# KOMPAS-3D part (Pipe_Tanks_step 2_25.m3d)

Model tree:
1. X Axis
2. Y Axis
3. Z Axis  (labels: Pipe Dn 50; T-Bend Dn 50)
     Òîëùèíà ñòåíêè 1 = 1

Referenced files in C:\Documents and Settings\kashirsky\Мои документы\Camtasia Studio\Pipelines3D\Tanks\: Tanks_step 2.a3d
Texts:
  Pipe Dn 50
  Steel ASTM A295
  Three Point Plane
  Plane at Angle
  Line and Point Plane
  Axis through Two Vertices
  Axis of Feature
  Axis of Conical Surface
  Axis through Edge
  Trim by Surface
  Trim by Sketch
  Feature with No History
  Intersection Axis of Two Planes
  Two Line Plane
  Line and Face Plane
  Bend by line
  Hole in sheet body
  Cut in sheet body
  Point in CM
  Linear Dimension from Line to Point
  Surface Finish Symbol
  Geometric Tolerance Symbol
  Leader #1
  Leader #2
  Leader #3
  Shape Deviations and Datum
  Node point number
  Mark of coordination axis
  Node point designation
  Mark/Reference designation with leader
  Mark/reference designation on line
  Mark/Reference designation without leader
  T-Bend Dn 50
  Plane of section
